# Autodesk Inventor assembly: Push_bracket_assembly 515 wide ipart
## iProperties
Shininess: 20.0
Length Units: 11269
Angle Units: 11279
Time Units: 11290
Mass Units: 11283
Length Display Precision: 3
Angle Display Precision: 2
Created: 2001-05
Part Number: Push_bracket_assembly 515 wide ipart
Document SubType Name: Baugruppe
Designer: dl
Density: 0.0
Volumn: 0.0
Area: 0.0
PropertySet Name: Model Information
Control State: 0
Master: False
Checked Out: False
Author: dl
